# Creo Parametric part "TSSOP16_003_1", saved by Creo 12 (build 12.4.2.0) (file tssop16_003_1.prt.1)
Units: Custom; MM, KILOGRAM, SECS

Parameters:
  PTC_WM_ITERATION = "0"
  PTC_WM_VERSION = "-.0"
  PTC_WM_LIFECYCLE_STATE = "In Work"
  PTC_WM_LIFECYCLE = "MO_CADDocument"
  PTC_WM_CREATED_BY = "Maximilian Roepper (Z0017RMS: MO)"
  PTC_WM_CREATED_ON = "18-Sep-26 11:36:42 AM"
  PTC_WM_MODIFIED_BY = "Maximilian Roepper (Z0017RMS: MO)"
  PTC_WM_MODIFIED_ON = "18-Sep-26 11:36:46 AM"
  PDMLINKNUMBER = "PDM000071455009"
  PTC_WM_NAME = "tssop16_003_1.prt"
  PTC_WM_NUMBER = "PDM000071455009"

Other parameters: WEIGHT, WEIGHT_FACTOR, WEIGHT_ADD, _MASS_TEMP, _DIFF_TEMP, MC_ERRORS, SUPPLIER

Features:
  1. coordinate system
  2. datum plane "PRT_YZ"
  3. datum plane "PRT_XY"
  4. datum plane "PRT_XZ"
  5. coordinate system
  6. datum axis
  7. datum axis
  8. datum axis
  9. coordinate system
  10. imported feature

Other named items: PRT, SIEMENS_MO, DRW_VIEW_ORG, PRT_X, PRT_Y, PRT_Z, CS0, ROUGH_GROB

Layers: 00_STD_CSYS-KSYS, 01_STD_PLANES-EBENEN, 02_STD_AXES-ACHSEN, 03_STD_CSYS-KSYS, 24_IMPORT_FEAT-IMPORT_KE

Surfaces: 14 plane, 8 cylinder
